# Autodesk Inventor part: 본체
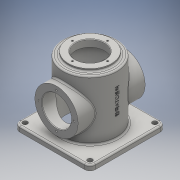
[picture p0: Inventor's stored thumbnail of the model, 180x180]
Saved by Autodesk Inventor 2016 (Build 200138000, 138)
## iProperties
Created: 2019-08
Part Number: 본체
Material: 일반
Document SubType Name: Modeling
Designer: user
Density: 1 g/cm^3
Appearance: 기본값
Author: user
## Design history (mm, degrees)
sketch "스케치1"
  geometry: L1 (70, -70)-(-70, -70); L2 (-70, -70)-(-70, 70); L3 (-70, 70)-(70, 70); L4 (70, 70)-(70, -70); L5 (70, -70)-(-70, 70); L6 (-70, -70)-(70, 70); 1 further point
  constraints: 12 end point, 2 midpoint, 2 parallel, 1 horizontal, 1 perpendicular
  dimensions: "d0" = 140 distance of L2.end L3.end; "d1" = 140 distance of L1.end L2.end
extrude "돌출1" new body sketch "스케치1" distance "d2" = 10; taper "d3" = 0 deg
sketch "스케치2"
  geometry: C1 r 50 at (0, 0); 1 further point
  constraints: 1 centre point, 1 coincident
  dimensions: "d4" = 100 diameter of C1
extrude "돌출2" join sketch "스케치2" distance "d5" = 110; taper "d6" = 0 deg
sketch "스케치3"
  geometry: C1 r 40 at (0, 0); 1 further point
  constraints: 1 centre point, 1 coincident
  dimensions: "d7" = 80 diameter of C1
extrude "돌출3" join sketch "스케치3" distance "d8" = 5; taper "d9" = 0 deg
sketch "스케치6"
  geometry: C1 r 27 at (0, 0); 1 further point
  constraints: 1 centre point, 1 coincident
  dimensions: "d11" = 54 diameter of C1
hole "구멍1" sketch "스케치6" at (0, 0) diameter "d12" = 54; stored, may be unused: countersink angle "d16" = 90 deg, drill point angle "d18" = 0 deg; dims "d13" = 6, "d14" = 4, "d15" = 2, "d17" = 13
node "작업 평면1"
sketch "스케치9"
  geometry: L1 (-70, 0)-(70, 0) reference; C1 r 40 at (0, 60); 2 further points
  constraints: 1 centre point, 1 midpoint, 1 vertical alignment
  dimensions: "d28" = 80 diameter of C1; "d29" = 60 distance from line of L1 C1.centre
extrude "돌출4" join sketch "스케치9" stored distance "d30" = 12; taper "d31" = 0 deg
fillet "모깎기1" dims "d32" = 10
hole "구멍3" diameter "d35" = 9; stored, may be unused: countersink angle "d39" = 90 deg, drill point angle "d41" = 0 deg; dims "d33" = 10, "d34" = 10, "d36" = 6, "d37" = 4, "d38" = 2, "d40" = 112
sketch "스케치12"
  geometry: 2 further points
  constraints: 1 vertical alignment
  dimensions: "d49" = 32.5 distance of point (0, 0) point (0, 32.5)
hole "구멍4" sketch "스케치12" at (0, 32.5) diameter "d50" = 3.242; stored, may be unused: countersink angle "d54" = 90 deg, drill point angle "d56" = 118 deg; dims "d51" = 8, "d52" = 4, "d53" = 2, "d55" = 10
fillet "모깎기2" dims "d60" = 3
fillet "모깎기3" dims "d61" = 3
hole "구멍5" diameter "d64" = 54; stored, may be unused: countersink angle "d68" = 90 deg, drill point angle "d70" = 0 deg; dims "d62" = 10, "d63" = 10, "d65" = 8, "d66" = 4, "d67" = 2, "d69" = 10
sketch "스케치15"
  geometry: C1 r 27 at (0, 0) reference; C2 r 40 at (0, 0) reference; 2 further points
  constraints: 1 vertical alignment
  dimensions: "d71" = 32.5 distance of C1.centre point (0, 32.5)
hole "구멍6" sketch "스케치15" at (0, 32.5) diameter "d72" = 3.242; stored, may be unused: countersink angle "d76" = 90 deg, drill point angle "d78" = 118 deg; dims "d73" = 8, "d74" = 4, "d75" = 2, "d77" = 11
fillet "모깎기4" dims "d82" = 3
chamfer "모따기1" distance "d83" = 1; stored, may be unused: second distance "d84" = 2, angle "d85" = 45 deg
sketch "스케치17"
  geometry: C1 r 45 at (0, 0); 1 further point
  constraints: 1 centre point, 1 coincident
  dimensions: "d86" = 90 diameter of C1
hole "구멍7" sketch "스케치17" at (0, 0) diameter "d87" = 90; stored, may be unused: countersink angle "d91" = 90 deg, drill point angle "d93" = 0 deg; dims "d88" = 8, "d89" = 4, "d90" = 2, "d92" = 112
fillet "모깎기6" dims "d95" = 3
chamfer "모따기2" distance "d96" = 1; stored, may be unused: second distance "d97" = 2, angle "d98" = 45 deg
chamfer "모따기3" distance "d99" = 1; stored, may be unused: second distance "d100" = 2, angle "d101" = 45 deg
fillet "모깎기7" dims "d102" = 3
fillet "모깎기8" dims "d103" = 3
node "작업 평면2"
sketch "스케치23" dims "d0" = 140, "d1" = 140
  geometry: L1 (60, 0)-(-60, 0) reference; 3 further points
  constraints: 1 midpoint, 1 vertical alignment, 1 other
  dimensions: "d105" = 70 distance from line of L1 point (0, 70)
feature "엠보싱1" sketch "스케치23" dims "d106" = 0.5, "d107" = 0
node "솔리드1"
mirror "대칭1"
pattern_linear "직사각형 패턴1" dims "d44" = 120
pattern_circular "원형 패턴1" dims angle "d58" = 360 deg
pattern_circular "원형 패턴2" dims angle "d80" = 360 deg
mirror "대칭2"
node "투영된 루프4"
other parameters: "d27" = -62, "d104" = 64.75
